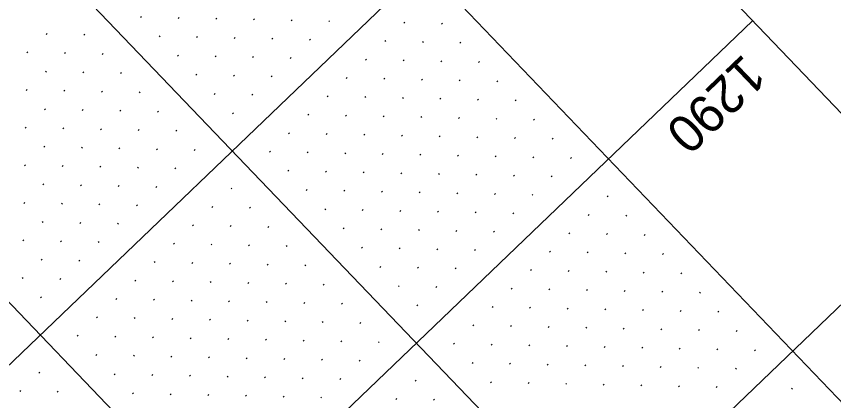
# Model space of a CAD drawing. Extents: x 2148987 to 2151117, y 142806 to 144993.
# Drawn here: x 2150296.6 to 2150450.2, y 144432.4 to 144504.6 of the extents above; entities that cross this region are included whole.
import ezdxf

# ---------------------------------------------------------------- set-up
doc = ezdxf.new("R2010")
doc.units = 0
for name, color, linetype in [('PR_PIER_PH3', 7, 'Continuous'), ('PR_Road_Concrete', 7, 'Continuous'), ('SHT_Profile_Grid_Minor', 7, 'Continuous'), ('Wall D Bore', 7, 'Continuous')]:
    doc.layers.add(name, color=color, linetype=linetype)

msp = doc.modelspace()

# ---------------------------------------------------------------- linework, layer by layer
at = {"layer": 'PR_PIER_PH3'}
for p, q in [((2150164.2, 144659.82), (2150510.15, 144298.83)), ((2150128.1, 144625.23), (2150449.83, 144289.5)), ((2150400.35, 144539.87), (2149263.21, 143450.12)), ((2150434.94, 144503.77), (2149297.81, 143414.02)), ((2150469.54, 144467.67), (2149332.4, 143377.92))]:
    msp.add_line(p, q, dxfattribs=at)
at = {"layer": 'PR_Road_Concrete'}
msp.add_line((2150200.3, 144694.42), (2150546.25, 144333.42), dxfattribs=at)
msp.add_lwpolyline([(2150941.76, 143974.91), (2149804.63, 142885.16), (2149078.13, 143643.25), (2150215.26, 144733)], close=True, dxfattribs=at)
at = {"layer": 'SHT_Profile_Grid_Minor'}
for p, q in [((2150320.12, 144504.53), (2150319.94, 144504.36)), ((2150327.19, 144504.38), (2150327.01, 144504.21)), ((2150334.26, 144504.23), (2150334.08, 144504.06)), ((2150341.33, 144504.08), (2150341.14, 144503.91)), ((2150348.39, 144503.93), (2150348.21, 144503.76)), ((2150355.46, 144503.78), (2150355.28, 144503.61)), ((2150369.6, 144503.48), (2150369.42, 144503.3)), ((2150376.67, 144503.33), (2150376.49, 144503.15)), ((2150302.37, 144501.37), (2150302.19, 144501.2)), ((2150309.44, 144501.22), (2150309.26, 144501.05)), ((2150323.58, 144500.92), (2150323.4, 144500.75)), ((2150330.65, 144500.77), (2150330.47, 144500.6)), ((2150337.72, 144500.62), (2150337.53, 144500.45)), ((2150344.78, 144500.47), (2150344.6, 144500.3)), ((2150351.85, 144500.32), (2150351.67, 144500.15)), ((2150365.99, 144500.02), (2150365.81, 144499.84)), ((2150373.06, 144499.87), (2150372.88, 144499.69)), ((2150380.13, 144499.72), (2150379.95, 144499.54)), ((2150298.76, 144497.91), (2150298.58, 144497.74)), ((2150305.83, 144497.76), (2150305.65, 144497.59)), ((2150312.9, 144497.61), (2150312.72, 144497.44)), ((2150327.04, 144497.31), (2150326.86, 144497.14)), ((2150334.11, 144497.16), (2150333.92, 144496.99)), ((2150341.17, 144497.01), (2150340.99, 144496.84)), ((2150348.24, 144496.86), (2150348.06, 144496.69)), ((2150362.38, 144496.56), (2150362.2, 144496.39)), ((2150369.45, 144496.41), (2150369.27, 144496.23)), ((2150376.52, 144496.26), (2150376.34, 144496.08)), ((2150383.59, 144496.11), (2150383.41, 144495.93)), ((2150302.22, 144494.3), (2150302.04, 144494.13)), ((2150309.29, 144494.15), (2150309.11, 144493.98)), ((2150316.36, 144494), (2150316.18, 144493.83)), ((2150330.5, 144493.7), (2150330.31, 144493.53)), ((2150337.56, 144493.55), (2150337.38, 144493.38)), ((2150344.63, 144493.4), (2150344.45, 144493.23)), ((2150358.77, 144493.1), (2150358.59, 144492.93)), ((2150365.84, 144492.95), (2150365.66, 144492.78)), ((2150372.91, 144492.8), (2150372.73, 144492.62)), ((2150379.98, 144492.65), (2150379.8, 144492.47)), ((2150387.05, 144492.5), (2150386.87, 144492.32)), ((2150298.61, 144490.84), (2150298.43, 144490.67)), ((2150305.68, 144490.69), (2150305.5, 144490.52)), ((2150312.75, 144490.54), (2150312.57, 144490.37)), ((2150319.82, 144490.39), (2150319.64, 144490.22)), ((2150333.95, 144490.09), (2150333.77, 144489.92)), ((2150341.02, 144489.94), (2150340.84, 144489.77)), ((2150355.16, 144489.64), (2150354.98, 144489.47)), ((2150362.23, 144489.49), (2150362.05, 144489.32)), ((2150369.3, 144489.34), (2150369.12, 144489.17)), ((2150376.37, 144489.19), (2150376.19, 144489.01)), ((2150383.44, 144489.04), (2150383.26, 144488.86)), ((2150390.51, 144488.89), (2150390.33, 144488.71)), ((2150302.07, 144487.23), (2150301.89, 144487.06)), ((2150309.14, 144487.08), (2150308.96, 144486.91)), ((2150316.21, 144486.93), (2150316.03, 144486.76)), ((2150323.28, 144486.78), (2150323.09, 144486.61)), ((2150337.41, 144486.48), (2150337.23, 144486.31)), ((2150351.55, 144486.18), (2150351.37, 144486.01)), ((2150358.62, 144486.03), (2150358.44, 144485.86)), ((2150365.69, 144485.88), (2150365.51, 144485.71)), ((2150372.76, 144485.73), (2150372.58, 144485.56)), ((2150379.83, 144485.58), (2150379.65, 144485.4)), ((2150386.9, 144485.43), (2150386.72, 144485.25)), ((2150393.97, 144485.28), (2150393.79, 144485.1)), ((2150298.46, 144483.77), (2150298.28, 144483.6)), ((2150305.53, 144483.62), (2150305.35, 144483.45)), ((2150312.6, 144483.47), (2150312.42, 144483.3)), ((2150319.67, 144483.32), (2150319.48, 144483.15)), ((2150326.73, 144483.17), (2150326.55, 144483)), ((2150347.94, 144482.72), (2150347.76, 144482.55)), ((2150355.01, 144482.57), (2150354.83, 144482.4)), ((2150362.08, 144482.42), (2150361.9, 144482.25)), ((2150369.15, 144482.27), (2150368.97, 144482.1)), ((2150376.22, 144482.12), (2150376.04, 144481.95)), ((2150383.29, 144481.97), (2150383.11, 144481.8)), ((2150390.36, 144481.82), (2150390.18, 144481.64)), ((2150397.43, 144481.67), (2150397.25, 144481.49)), ((2150301.92, 144480.16), (2150301.74, 144479.99)), ((2150308.99, 144480.01), (2150308.81, 144479.84)), ((2150316.06, 144479.86), (2150315.87, 144479.69)), ((2150323.12, 144479.71), (2150322.94, 144479.54)), ((2150330.19, 144479.56), (2150330.01, 144479.39)), ((2150344.33, 144479.26), (2150344.15, 144479.09)), ((2150351.4, 144479.11), (2150351.22, 144478.94)), ((2150358.47, 144478.96), (2150358.29, 144478.79)), ((2150365.54, 144478.81), (2150365.36, 144478.64)), ((2150372.61, 144478.66), (2150372.43, 144478.49)), ((2150379.68, 144478.51), (2150379.5, 144478.34)), ((2150386.75, 144478.36), (2150386.57, 144478.19)), ((2150393.82, 144478.21), (2150393.64, 144478.03)), ((2150400.89, 144478.06), (2150400.71, 144477.88)), ((2150298.31, 144476.7), (2150298.13, 144476.53)), ((2150305.38, 144476.55), (2150305.2, 144476.38)), ((2150312.45, 144476.4), (2150312.26, 144476.23)), ((2150319.51, 144476.25), (2150319.33, 144476.08)), ((2150326.58, 144476.1), (2150326.4, 144475.93)), ((2150347.79, 144475.65), (2150347.61, 144475.48)), ((2150354.86, 144475.5), (2150354.68, 144475.33)), ((2150361.93, 144475.35), (2150361.75, 144475.18)), ((2150369, 144475.2), (2150368.82, 144475.03)), ((2150376.07, 144475.05), (2150375.89, 144474.88)), ((2150383.14, 144474.9), (2150382.96, 144474.73)), ((2150390.21, 144474.75), (2150390.03, 144474.58)), ((2150397.28, 144474.6), (2150397.1, 144474.42)), ((2150301.77, 144473.09), (2150301.59, 144472.92)), ((2150308.84, 144472.94), (2150308.65, 144472.77)), ((2150315.9, 144472.79), (2150315.72, 144472.62)), ((2150322.97, 144472.64), (2150322.79, 144472.47)), ((2150337.11, 144472.34), (2150336.93, 144472.17)), ((2150351.25, 144472.04), (2150351.07, 144471.87)), ((2150358.32, 144471.89), (2150358.14, 144471.72)), ((2150365.39, 144471.74), (2150365.21, 144471.57)), ((2150372.46, 144471.59), (2150372.28, 144471.42)), ((2150379.53, 144471.44), (2150379.35, 144471.27)), ((2150386.6, 144471.29), (2150386.42, 144471.12)), ((2150393.67, 144471.14), (2150393.49, 144470.97)), ((2150407.81, 144470.84), (2150407.63, 144470.66)), ((2150298.16, 144469.63), (2150297.98, 144469.46)), ((2150305.23, 144469.48), (2150305.05, 144469.31)), ((2150312.29, 144469.33), (2150312.11, 144469.16)), ((2150319.36, 144469.18), (2150319.18, 144469.01)), ((2150333.5, 144468.88), (2150333.32, 144468.71)), ((2150340.57, 144468.73), (2150340.39, 144468.56)), ((2150354.71, 144468.43), (2150354.53, 144468.26)), ((2150361.78, 144468.28), (2150361.6, 144468.11)), ((2150368.85, 144468.13), (2150368.67, 144467.96)), ((2150375.92, 144467.98), (2150375.74, 144467.81)), ((2150382.99, 144467.83), (2150382.81, 144467.66)), ((2150390.06, 144467.68), (2150389.88, 144467.51)), ((2150404.2, 144467.38), (2150404.02, 144467.2)), ((2150411.27, 144467.23), (2150411.09, 144467.05)), ((2150301.62, 144466.02), (2150301.44, 144465.85)), ((2150308.69, 144465.87), (2150308.5, 144465.7)), ((2150315.75, 144465.72), (2150315.57, 144465.55)), ((2150329.89, 144465.42), (2150329.71, 144465.25)), ((2150336.96, 144465.27), (2150336.78, 144465.1)), ((2150344.03, 144465.12), (2150343.85, 144464.95)), ((2150358.17, 144464.82), (2150357.99, 144464.65)), ((2150365.24, 144464.67), (2150365.06, 144464.5)), ((2150372.31, 144464.52), (2150372.13, 144464.35)), ((2150379.38, 144464.37), (2150379.2, 144464.2)), ((2150386.45, 144464.22), (2150386.27, 144464.05)), ((2150298.01, 144462.56), (2150297.83, 144462.39)), ((2150400.59, 144463.92), (2150400.41, 144463.75)), ((2150407.66, 144463.77), (2150407.48, 144463.59)), ((2150414.73, 144463.62), (2150414.55, 144463.44)), ((2150305.08, 144462.41), (2150304.89, 144462.24)), ((2150312.14, 144462.26), (2150311.96, 144462.09)), ((2150326.28, 144461.96), (2150326.1, 144461.79)), ((2150333.35, 144461.81), (2150333.17, 144461.64)), ((2150340.42, 144461.66), (2150340.24, 144461.49)), ((2150347.49, 144461.51), (2150347.31, 144461.34)), ((2150361.63, 144461.21), (2150361.45, 144461.04)), ((2150368.7, 144461.06), (2150368.52, 144460.89)), ((2150375.77, 144460.91), (2150375.59, 144460.74)), ((2150382.84, 144460.76), (2150382.66, 144460.59)), ((2150396.98, 144460.46), (2150396.8, 144460.29)), ((2150404.05, 144460.31), (2150403.87, 144460.14)), ((2150411.12, 144460.16), (2150410.94, 144459.98)), ((2150418.19, 144460.01), (2150418.01, 144459.83)), ((2150301.47, 144458.95), (2150301.28, 144458.78)), ((2150308.53, 144458.8), (2150308.35, 144458.63)), ((2150322.67, 144458.5), (2150322.49, 144458.33)), ((2150329.74, 144458.35), (2150329.56, 144458.18)), ((2150336.81, 144458.2), (2150336.63, 144458.03)), ((2150343.88, 144458.05), (2150343.7, 144457.88)), ((2150350.95, 144457.9), (2150350.77, 144457.73)), ((2150365.09, 144457.6), (2150364.91, 144457.43)), ((2150372.16, 144457.45), (2150371.98, 144457.28)), ((2150379.23, 144457.3), (2150379.05, 144457.13)), ((2150393.37, 144457), (2150393.19, 144456.83)), ((2150400.44, 144456.85), (2150400.26, 144456.68)), ((2150407.51, 144456.7), (2150407.33, 144456.53)), ((2150414.58, 144456.55), (2150414.4, 144456.37)), ((2150297.86, 144455.5), (2150297.67, 144455.32)), ((2150304.92, 144455.34), (2150304.74, 144455.17)), ((2150319.06, 144455.04), (2150318.88, 144454.87)), ((2150326.13, 144454.89), (2150325.95, 144454.72)), ((2150421.65, 144456.4), (2150421.47, 144456.22)), ((2150333.2, 144454.74), (2150333.02, 144454.57)), ((2150340.27, 144454.59), (2150340.09, 144454.42)), ((2150347.34, 144454.44), (2150347.16, 144454.27)), ((2150354.41, 144454.29), (2150354.23, 144454.12)), ((2150368.55, 144453.99), (2150368.37, 144453.82)), ((2150375.62, 144453.84), (2150375.44, 144453.67)), ((2150389.76, 144453.54), (2150389.58, 144453.37)), ((2150396.83, 144453.39), (2150396.65, 144453.22)), ((2150301.31, 144451.89), (2150301.13, 144451.71)), ((2150403.9, 144453.24), (2150403.72, 144453.07)), ((2150410.97, 144453.09), (2150410.79, 144452.92)), ((2150418.04, 144452.94), (2150417.86, 144452.76)), ((2150425.11, 144452.79), (2150424.93, 144452.61)), ((2150315.45, 144451.58), (2150315.27, 144451.41)), ((2150322.52, 144451.43), (2150322.34, 144451.26)), ((2150329.59, 144451.28), (2150329.41, 144451.11)), ((2150336.66, 144451.13), (2150336.48, 144450.96)), ((2150343.73, 144450.98), (2150343.55, 144450.81)), ((2150350.8, 144450.83), (2150350.62, 144450.66)), ((2150357.87, 144450.68), (2150357.69, 144450.51)), ((2150372.01, 144450.38), (2150371.83, 144450.21)), ((2150386.15, 144450.08), (2150385.97, 144449.91)), ((2150393.22, 144449.93), (2150393.04, 144449.76)), ((2150400.29, 144449.78), (2150400.11, 144449.61)), ((2150407.36, 144449.63), (2150407.18, 144449.46)), ((2150414.43, 144449.48), (2150414.25, 144449.31)), ((2150421.5, 144449.33), (2150421.32, 144449.15)), ((2150428.57, 144449.18), (2150428.38, 144449)), ((2150311.84, 144448.13), (2150311.66, 144447.95)), ((2150318.91, 144447.97), (2150318.73, 144447.8)), ((2150325.98, 144447.82), (2150325.8, 144447.65)), ((2150333.05, 144447.67), (2150332.87, 144447.5)), ((2150340.12, 144447.52), (2150339.94, 144447.35)), ((2150347.19, 144447.37), (2150347.01, 144447.2)), ((2150354.26, 144447.22), (2150354.08, 144447.05)), ((2150361.33, 144447.07), (2150361.15, 144446.9)), ((2150382.54, 144446.62), (2150382.36, 144446.45)), ((2150389.61, 144446.47), (2150389.43, 144446.3)), ((2150396.68, 144446.32), (2150396.5, 144446.15)), ((2150403.75, 144446.17), (2150403.57, 144446)), ((2150410.82, 144446.02), (2150410.64, 144445.85)), ((2150417.89, 144445.87), (2150417.71, 144445.7)), ((2150424.96, 144445.72), (2150424.77, 144445.55)), ((2150308.23, 144444.67), (2150308.05, 144444.49)), ((2150315.3, 144444.52), (2150315.12, 144444.34)), ((2150322.37, 144444.36), (2150322.19, 144444.19)), ((2150329.44, 144444.21), (2150329.26, 144444.04)), ((2150432.02, 144445.57), (2150431.84, 144445.39)), ((2150336.51, 144444.06), (2150336.33, 144443.89)), ((2150343.58, 144443.91), (2150343.4, 144443.74)), ((2150350.65, 144443.76), (2150350.47, 144443.59)), ((2150357.72, 144443.61), (2150357.54, 144443.44)), ((2150364.79, 144443.46), (2150364.61, 144443.29)), ((2150378.93, 144443.16), (2150378.75, 144442.99)), ((2150386, 144443.01), (2150385.82, 144442.84)), ((2150393.07, 144442.86), (2150392.89, 144442.69)), ((2150400.14, 144442.71), (2150399.96, 144442.54)), ((2150311.69, 144441.06), (2150311.51, 144440.88)), ((2150407.21, 144442.56), (2150407.03, 144442.39)), ((2150414.28, 144442.41), (2150414.1, 144442.24)), ((2150421.35, 144442.26), (2150421.16, 144442.09)), ((2150428.41, 144442.11), (2150428.23, 144441.94)), ((2150435.48, 144441.96), (2150435.3, 144441.78)), ((2150318.76, 144440.91), (2150318.58, 144440.73)), ((2150325.83, 144440.75), (2150325.65, 144440.58)), ((2150332.9, 144440.6), (2150332.72, 144440.43)), ((2150339.97, 144440.45), (2150339.79, 144440.28)), ((2150347.04, 144440.3), (2150346.86, 144440.13)), ((2150354.11, 144440.15), (2150353.93, 144439.98)), ((2150361.18, 144440), (2150361, 144439.83)), ((2150382.39, 144439.55), (2150382.21, 144439.38)), ((2150389.46, 144439.4), (2150389.28, 144439.23)), ((2150396.53, 144439.25), (2150396.35, 144439.08)), ((2150403.6, 144439.1), (2150403.42, 144438.93)), ((2150410.67, 144438.95), (2150410.49, 144438.78)), ((2150417.74, 144438.8), (2150417.55, 144438.63)), ((2150424.8, 144438.65), (2150424.62, 144438.48)), ((2150431.87, 144438.5), (2150431.69, 144438.33)), ((2150301.01, 144437.75), (2150300.83, 144437.57)), ((2150315.15, 144437.45), (2150314.97, 144437.27)), ((2150322.22, 144437.3), (2150322.04, 144437.12)), ((2150329.29, 144437.14), (2150329.11, 144436.97)), ((2150336.36, 144436.99), (2150336.18, 144436.82)), ((2150343.43, 144436.84), (2150343.25, 144436.67)), ((2150350.5, 144436.69), (2150350.32, 144436.52)), ((2150357.57, 144436.54), (2150357.39, 144436.37)), ((2150371.71, 144436.24), (2150371.53, 144436.07)), ((2150385.85, 144435.94), (2150385.67, 144435.77)), ((2150392.92, 144435.79), (2150392.74, 144435.62)), ((2150399.99, 144435.64), (2150399.81, 144435.47)), ((2150407.06, 144435.49), (2150406.88, 144435.32)), ((2150414.13, 144435.34), (2150413.94, 144435.17)), ((2150421.19, 144435.19), (2150421.01, 144435.02)), ((2150428.26, 144435.04), (2150428.08, 144434.87)), ((2150297.4, 144434.29), (2150297.22, 144434.11)), ((2150304.47, 144434.14), (2150304.29, 144433.96)), ((2150318.61, 144433.84), (2150318.43, 144433.66)), ((2150325.68, 144433.69), (2150325.5, 144433.51)), ((2150332.75, 144433.53), (2150332.57, 144433.36)), ((2150339.82, 144433.38), (2150339.64, 144433.21)), ((2150442.4, 144434.74), (2150442.22, 144434.56)), ((2150346.89, 144433.23), (2150346.71, 144433.06)), ((2150353.96, 144433.08), (2150353.78, 144432.91)), ((2150368.1, 144432.78), (2150367.92, 144432.61)), ((2150375.17, 144432.63), (2150374.99, 144432.46))]:
    msp.add_line(p, q, dxfattribs=at)

# ---------------------------------------------------------------- texts
at = {"layer": 'Wall D Bore'}
msp.add_text('1290', height=7, rotation=223.7809, dxfattribs=at).set_placement((2150433.23, 144497.75))

doc.saveas('drawing.dxf')
